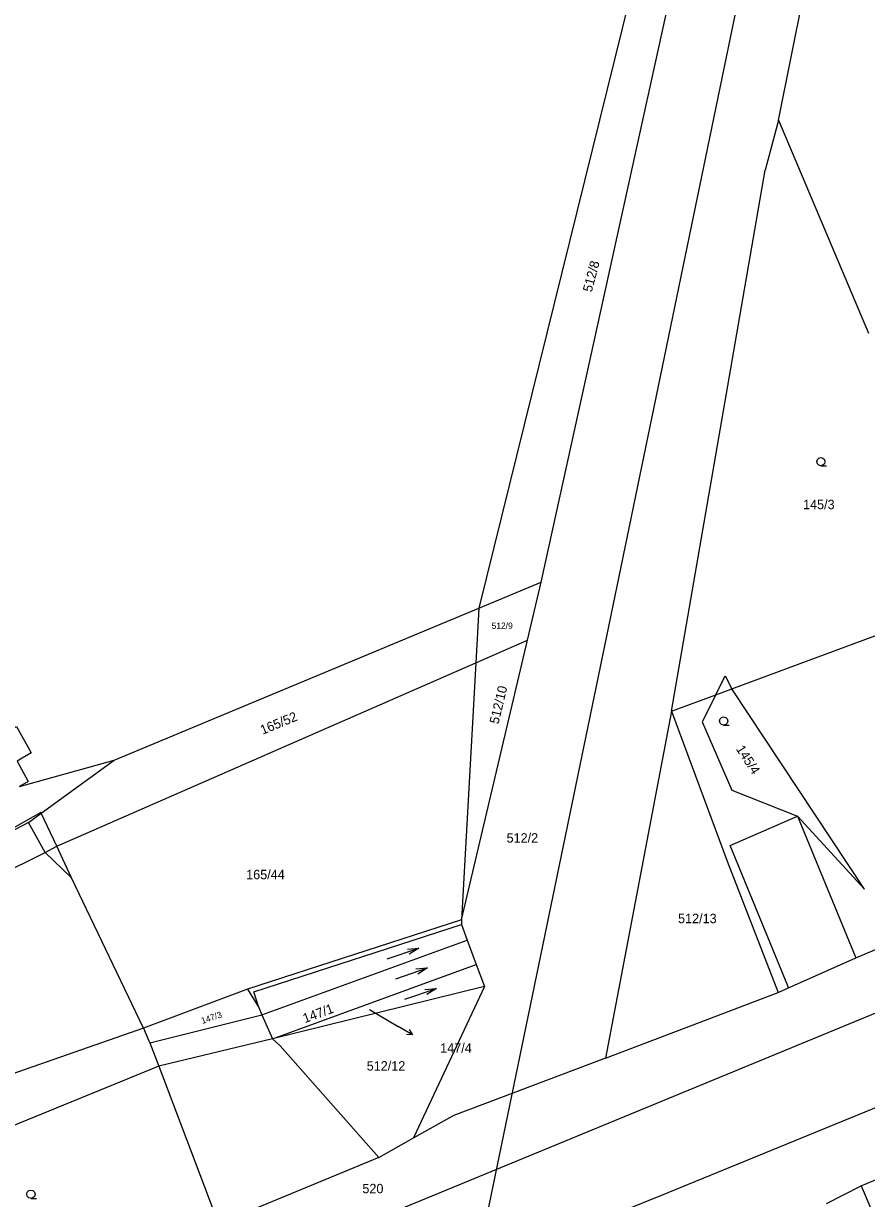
# Model space of a CAD drawing. Extents: x -757994 to -755874, y -1047691 to -1046119.
# Drawn here: x -756803.8 to -756727.8, y -1046913.1 to -1046807.2 of the extents above; entities that cross this region are included whole.
import ezdxf

# ---------------------------------------------------------------- set-up
doc = ezdxf.new("R2010")
doc.units = 0
doc.layers.add('katastrální mapa', color=7, linetype='Continuous')

msp = doc.modelspace()

# ---------------------------------------------------------------- linework, layer by layer
at = {"layer": 'katastrální mapa'}
for p, q in [((-756757.13, -1046857.54), (-756739.22, -1046776)), ((-756736.73, -1046792.06), (-756764.8, -1046928)), ((-756747.05, -1046796.22), (-756762.76, -1046859.88)), ((-756735.77, -1046815.87), (-756732.14, -1046797.84)), ((-756735.77, -1046815.87), (-756736.96, -1046820.4)), ((-756735.77, -1046815.87), (-756727.66, -1046835.08)), ((-756745.4, -1046869.16), (-756736.96, -1046820.4)), ((-756745.69, -1046904.09), (-756612.98, -1046849.23)), ((-756762.76, -1046859.88), (-756757.13, -1046857.54)), ((-756758.36, -1046862.76), (-756757.13, -1046857.54)), ((-756739.97, -1046867.14), (-756717.72, -1046858.89)), ((-756795.62, -1046873.59), (-756762.76, -1046859.88)), ((-756762.76, -1046859.88), (-756763.03, -1046864.81)), ((-756764.31, -1046887.97), (-756758.36, -1046862.76)), ((-756763.03, -1046864.81), (-756758.36, -1046862.76)), ((-756800.79, -1046881.32), (-756763.03, -1046864.81)), ((-756763.03, -1046864.81), (-756764.31, -1046887.97)), ((-756741.42, -1046867.68), (-756740.58, -1046865.98)), ((-756740.58, -1046865.98), (-756739.97, -1046867.14)), ((-756745.4, -1046869.16), (-756741.42, -1046867.68)), ((-756741.42, -1046867.68), (-756742.63, -1046870.13)), ((-756741.42, -1046867.68), (-756739.97, -1046867.14)), ((-756728.01, -1046885.21), (-756739.97, -1046867.14)), ((-756745.4, -1046869.16), (-756751.36, -1046900.43)), ((-756745.4, -1046869.16), (-756740.38, -1046882.68)), ((-756742.63, -1046870.13), (-756739.97, -1046876.28)), ((-756804.14, -1046875.94), (-756795.62, -1046873.59)), ((-756802.19, -1046878.36), (-756795.62, -1046873.59)), ((-756739.97, -1046876.28), (-756734.05, -1046878.63)), ((-756802.22, -1046878.29), (-756812, -1046883.78)), ((-756803.33, -1046879.19), (-756802.19, -1046878.36)), ((-756802.19, -1046878.36), (-756802.22, -1046878.29)), ((-756800.79, -1046881.32), (-756802.19, -1046878.36)), ((-756740.11, -1046881.26), (-756734.05, -1046878.63)), ((-756734.05, -1046878.63), (-756728.01, -1046885.21)), ((-756734.05, -1046878.63), (-756728.79, -1046891.38)), ((-756803.33, -1046879.19), (-756812, -1046883.78)), ((-756801.82, -1046881.9), (-756803.33, -1046879.19)), ((-756801.82, -1046881.9), (-756800.79, -1046881.32)), ((-756799.45, -1046884.19), (-756800.79, -1046881.32)), ((-756734.92, -1046893.92), (-756740.11, -1046881.26)), ((-756835.16, -1046898.47), (-756801.82, -1046881.9)), ((-756799.45, -1046884.19), (-756801.82, -1046881.9)), ((-756740.38, -1046882.68), (-756735.8, -1046894.51)), ((-756792.96, -1046897.73), (-756799.45, -1046884.19)), ((-756764.31, -1046887.97), (-756783.59, -1046894.21)), ((-756764.31, -1046887.97), (-756764.33, -1046888.4)), ((-756728.79, -1046891.38), (-756720.27, -1046887.79)), ((-756783.04, -1046894.45), (-756764.33, -1046888.4)), ((-756764.33, -1046888.4), (-756763.81, -1046889.79)), ((-756782.3, -1046896.53), (-756763.81, -1046889.79)), ((-756763.81, -1046889.79), (-756762.99, -1046892)), ((-756771.01, -1046891.49), (-756768.17, -1046890.51)), ((-756734.85, -1046894.09), (-756728.79, -1046891.38)), ((-756781.35, -1046898.7), (-756762.99, -1046892)), ((-756770.23, -1046893.29), (-756767.39, -1046892.31)), ((-756762.99, -1046892), (-756762.25, -1046893.99)), ((-756746.37, -1046912.83), (-756698.86, -1046893.31)), ((-756783.59, -1046894.21), (-756792.96, -1046897.73)), ((-756783.59, -1046894.21), (-756782.58, -1046895.88)), ((-756782.58, -1046895.88), (-756783.04, -1046894.45)), ((-756762.25, -1046893.99), (-756781.35, -1046898.7)), ((-756769.42, -1046895.13), (-756766.58, -1046894.15)), ((-756762.25, -1046893.99), (-756768.63, -1046907.62)), ((-756751.36, -1046900.43), (-756735.8, -1046894.51)), ((-756735.8, -1046894.51), (-756734.85, -1046894.09)), ((-756734.85, -1046894.09), (-756734.92, -1046893.92)), ((-756792.41, -1046899.07), (-756782.3, -1046896.53)), ((-756782.58, -1046895.88), (-756782.3, -1046896.53)), ((-756782.3, -1046896.53), (-756781.35, -1046898.7)), ((-756772.61, -1046896.05), (-756770.02, -1046897.58)), ((-756792.96, -1046897.73), (-756822.69, -1046908.14)), ((-756792.96, -1046897.73), (-756792.49, -1046898.89)), ((-756768.73, -1046898.34), (-756770.02, -1046897.58)), ((-756781.35, -1046898.7), (-756791.58, -1046901.17)), ((-756781.35, -1046898.7), (-756780.67, -1046899.34)), ((-756792.49, -1046898.89), (-756792.41, -1046899.07)), ((-756792.41, -1046899.07), (-756791.58, -1046901.17)), ((-756780.67, -1046899.34), (-756771.78, -1046909.4)), ((-756751.36, -1046900.43), (-756765.11, -1046905.64)), ((-756791.58, -1046901.17), (-756819.77, -1046912.66)), ((-756791.58, -1046901.17), (-756786.2, -1046915.37)), ((-756783.55, -1046919.66), (-756745.69, -1046904.09)), ((-756768.63, -1046907.62), (-756765.11, -1046905.64)), ((-756771.78, -1046909.4), (-756768.63, -1046907.62)), ((-756771.78, -1046909.4), (-756786.2, -1046915.37)), ((-756728.3, -1046911.96), (-756723.6, -1046909.92)), ((-756731.43, -1046913.55), (-756728.3, -1046911.96)), ((-756773.92, -1046923.88), (-756746.37, -1046912.83))]:
    msp.add_line(p, q, dxfattribs=at)
for points in [[(-756731.94, -1046847.03), (-756732.13, -1046846.98), (-756732.26, -1046846.85), (-756732.32, -1046846.66), (-756732.26, -1046846.48), (-756732.13, -1046846.34), (-756731.95, -1046846.29), (-756731.76, -1046846.34), (-756731.62, -1046846.48), (-756731.58, -1046846.67), (-756731.62, -1046846.86), (-756731.76, -1046846.99), (-756731.95, -1046847.04), (-756731.45, -1046847.04)], [(-756819.74, -1046876.61), (-756806.75, -1046869.4), (-756805.71, -1046871.27), (-756804.41, -1046870.55), (-756803.09, -1046872.92), (-756804.36, -1046873.67), (-756803.35, -1046875.5), (-756804.14, -1046875.94)], [(-756740.7, -1046870.41), (-756740.89, -1046870.36), (-756741.02, -1046870.23), (-756741.08, -1046870.04), (-756741.02, -1046869.86), (-756740.89, -1046869.72), (-756740.71, -1046869.67), (-756740.52, -1046869.72), (-756740.39, -1046869.86), (-756740.34, -1046870.05), (-756740.39, -1046870.24), (-756740.52, -1046870.37), (-756740.71, -1046870.42), (-756740.21, -1046870.42)], [(-756769.2, -1046890.6), (-756768.17, -1046890.51), (-756769.04, -1046891.07)], [(-756768.42, -1046892.4), (-756767.39, -1046892.31), (-756768.26, -1046892.87)], [(-756767.61, -1046894.24), (-756766.58, -1046894.15), (-756767.45, -1046894.71)], [(-756769.03, -1046897.87), (-756768.73, -1046898.34), (-756769.29, -1046898.3)], [(-756728.3, -1046911.96), (-756723.61, -1046923.02), (-756715.86, -1046919.95), (-756715.49, -1046920.91), (-756710.42, -1046918.93), (-756714.18, -1046909.41), (-756714.84, -1046909.66), (-756715.07, -1046909.46), (-756715.8, -1046909.5), (-756717.01, -1046909.87), (-756718.14, -1046910.43), (-756718.68, -1046910.86), (-756718.56, -1046911.16), (-756722.36, -1046912.67), (-756723.6, -1046909.92)], [(-756803.11, -1046913.07), (-756803.3, -1046913.02), (-756803.44, -1046912.89), (-756803.48, -1046912.7), (-756803.44, -1046912.51), (-756803.3, -1046912.38), (-756803.11, -1046912.33), (-756802.93, -1046912.38), (-756802.79, -1046912.51), (-756802.74, -1046912.71), (-756802.79, -1046912.9), (-756802.93, -1046913.03), (-756803.12, -1046913.08), (-756802.62, -1046913.08)]]:
    msp.add_lwpolyline(points, dxfattribs=at)

# ---------------------------------------------------------------- texts
for s, height, rotation, p in [('512/8', 0.85, 75.2867, (-756752.59, -1046831.44)), ('512/10', 0.85, 76.4899, (-756760.99, -1046870.37)), ('165/52', 0.85, 22.4026, (-756782.24, -1046871.29)), ('145/4', 0.85, 302.9228, (-756739.63, -1046872.56)), ('147/1', 0.85, 20.2254, (-756778.43, -1046897.29)), ('147/3', 0.57, 18.6784, (-756787.66, -1046897.36))]:
    msp.add_text(s, height=height, rotation=rotation, dxfattribs=at).set_placement(p)
for s, height, p in [('145/3', 0.85, (-756733.55, -1046850.95)), ('512/9', 0.57, (-756761.61, -1046861.74)), ('512/2', 0.85, (-756760.26, -1046881.01)), ('165/44', 0.85, (-756783.72, -1046884.31)), ('512/13', 0.85, (-756744.81, -1046888.27)), ('147/4', 0.05, (-756772.7, -1046896.05)), ('147/4', 0.85, (-756766.24, -1046899.95)), ('512/12', 0.85, (-756772.86, -1046901.56)), ('520', 0.85, (-756773.25, -1046912.62))]:
    msp.add_text(s, height=height, dxfattribs=at).set_placement(p)

doc.saveas('drawing.dxf')
